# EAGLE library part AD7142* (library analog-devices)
Programmable Capacitance-to-Digital Converter with Environmental Compensation Source: http://www.analog.com/UploadedFiles/Data_Sheets/762180021AD7142_42_1_prd.pdf
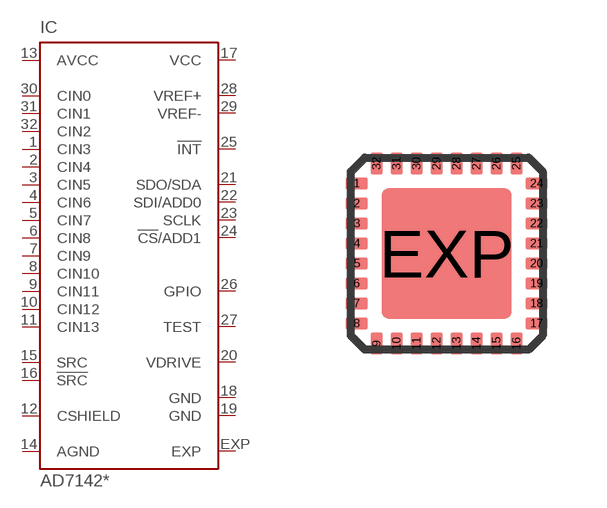
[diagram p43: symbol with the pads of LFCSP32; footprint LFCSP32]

Designator prefix IC

## AD7142-1ACPZ (MPN: AD7142ACPZ; OC_FARNELL: 1498724; OC_NEWARK: 15P0769), AD7142ACPZ (MPN: AD7142ACPZ; OC_FARNELL: 1498724; OC_NEWARK: 15P0769)  [LFCSP32]
1  CIN3  in
2  CIN4  in
3  CIN5  in
4  CIN6  in
5  CIN7  in
6  CIN8  in
7  CIN9  in
8  CIN10  in
9  CIN11  in
10  CIN12  in
11  CIN13  in
12  CSHIELD  out
13  AVCC  in
14  AGND  in
15  SRC  in
16  !SRC  in
17  VCC  pwr
18  GND  pwr
19  GND  pwr
20  VDRIVE  in
21  SDO/SDA  out
22  SDI/ADD0
23  SCLK  in
24  !CS!/ADD1  in
25  !INT  out
26  GPIO  in
27  TEST  in
28  VREF+  in
29  VREF-  in
30  CIN0  in
31  CIN1  in
32  CIN2  in
EXP  EXP  pas

## Footprint LFCSP32 (pad centres in mm)
32-Lead Frame Chip Scale Package [LFCSP_VQ] 5 mm × 5 mm Very Thin Quad (CP-32-3 COMPLIANT TO JEDEC STANDARDS MO-220-VHHD-2 Source: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
smd 0.55 x 0.3: 1 -2.25,1.75; 2 -2.25,1.25; 3 -2.25,0.75; 4 -2.25,0.25; 5 -2.25,-0.25; 6 -2.25,-0.75; 7 -2.25,-1.25; 8 -2.25,-1.75; 17 2.25,-1.75; 18 2.25,-1.25; 19 2.25,-0.75; 20 2.25,-0.25; 21 2.25,0.25; 22 2.25,0.75; 23 2.25,1.25; 24 2.25,1.75
smd 0.3 x 0.55: 9 -1.75,-2.25; 10 -1.25,-2.25; 11 -0.75,-2.25; 12 -0.25,-2.25; 13 0.25,-2.25; 14 0.75,-2.25; 15 1.25,-2.25; 16 1.75,-2.25; 25 1.75,2.25; 26 1.25,2.25; 27 0.75,2.25; 28 0.25,2.25; 29 -0.25,2.25; 30 -0.75,2.25; 31 -1.25,2.25; 32 -1.75,2.25
smd 3.25 x 3.25: EXP 0,0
